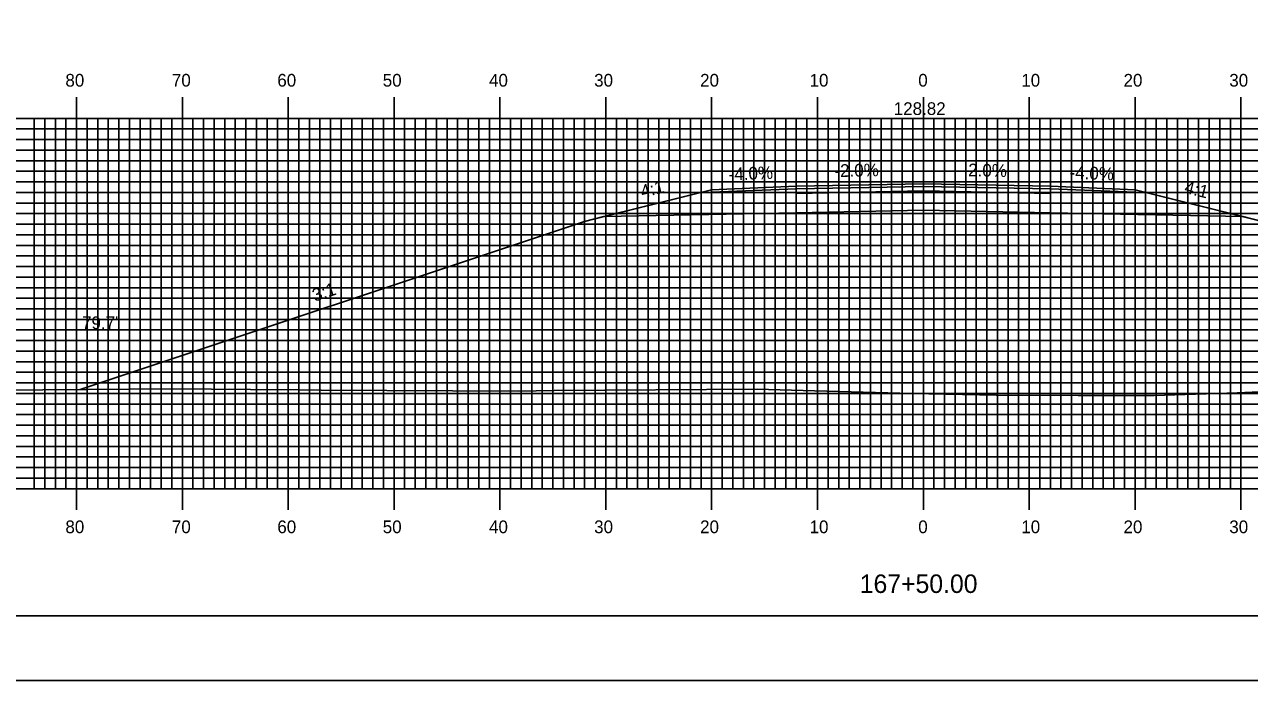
# Model space of a CAD drawing. Extents: x 1781860 to 1782203, y 442591 to 442811.
# Drawn here: x 1781941 to 1782056.7, y 442590.5 to 442652.5 of the extents above; entities that cross this region are included whole.
import ezdxf

# ---------------------------------------------------------------- set-up
doc = ezdxf.new("R2010")
doc.units = 0
for name, color, linetype in [('ANNOTATION', 7, 'Continuous'), ('BORDER', 7, 'Continuous'), ('D_Roadway_Centerline', 7, 'Continuous'), ('D_Roadway_Centerline_Text', 7, 'Continuous'), ('D_Roadway_Edge_Shoulder', 7, 'Continuous'), ('D_Roadway_Edge_TW', 7, 'Continuous'), ('D_Roadway_Pavement', 7, 'Continuous'), ('D_Roadway_SlopeLines', 7, 'Continuous'), ('D_Roadway_SubGrade', 7, 'Continuous'), ('D_Text_Standard', 7, 'Continuous'), ('H_V ANNOTATION', 7, 'Continuous'), ('MAJOR', 7, 'Continuous'), ('MINOR', 7, 'Continuous'), ('PLOT BOUNDARY', 7, 'Continuous'), ('S_Roadway_Centerline', 7, 'Continuous')]:
    doc.layers.add(name, color=color, linetype=linetype)

msp = doc.modelspace()

# ---------------------------------------------------------------- linework, layer by layer
at = {"layer": 'BORDER'}
msp.add_lwpolyline([(1781876.32, 442596.67), (1782196.32, 442596.67), (1782196.32, 442806.67), (1781876.32, 442806.67)], close=True, dxfattribs=at)
at = {"layer": 'D_Roadway_Centerline'}
msp.add_lwpolyline([(1781946.27, 442618.04), (1781993.92, 442633.93), (1781995.75, 442634.38), (1782005.92, 442636.93), (1782013.92, 442637.25), (1782025.92, 442637.49), (1782037.92, 442637.25), (1782045.92, 442636.93), (1782056.09, 442634.38), (1782057.92, 442633.93), (1782104.84, 442618.29)], dxfattribs=at)
at = {"layer": 'D_Roadway_Edge_Shoulder'}
for points in [[(1782013.92, 442637.25), (1782005.92, 442636.93), (1782005.92, 442636.68), (1782013.92, 442637)], [(1782037.92, 442637.25), (1782045.92, 442636.93), (1782045.92, 442636.68), (1782037.92, 442637)]]:
    msp.add_lwpolyline(points, close=True, dxfattribs=at)
at = {"layer": 'D_Roadway_Edge_TW'}
msp.add_lwpolyline([(1782013.92, 442637), (1782013.92, 442637.25), (1782025.92, 442637.49), (1782037.92, 442637.25), (1782037.92, 442637), (1782025.92, 442637.24)], close=True, dxfattribs=at)
at = {"layer": 'D_Roadway_Pavement'}
msp.add_lwpolyline([(1782013.92, 442636.58), (1782013.92, 442637), (1782025.92, 442637.24), (1782037.92, 442637), (1782037.92, 442636.58), (1782025.92, 442636.82)], close=True, dxfattribs=at)
at = {"layer": 'D_Roadway_SlopeLines'}
for points in [[(1782005.92, 442636.93), (1781993.92, 442633.93), (1781946.27, 442618.04)], [(1782045.92, 442636.93), (1782057.92, 442633.93), (1782104.84, 442618.29)]]:
    msp.add_lwpolyline(points, dxfattribs=at)
at = {"layer": 'D_Roadway_SubGrade'}
msp.add_lwpolyline([(1782013.92, 442634.75), (1781995.75, 442634.38), (1782005.92, 442636.93), (1782005.92, 442636.68), (1782013.92, 442637), (1782025.92, 442637.24), (1782037.92, 442637), (1782045.92, 442636.68), (1782045.92, 442636.93), (1782056.09, 442634.38), (1782037.92, 442634.75), (1782025.92, 442634.99)], close=True, dxfattribs=at)
at = {"layer": 'MAJOR'}
for p, q in [((1781945.92, 442645.67), (1781945.92, 442643.67)), ((1781955.92, 442645.67), (1781955.92, 442643.67)), ((1781965.92, 442645.67), (1781965.92, 442643.67)), ((1781975.92, 442645.67), (1781975.92, 442643.67)), ((1781985.92, 442645.67), (1781985.92, 442643.67)), ((1781995.92, 442645.67), (1781995.92, 442643.67)), ((1782005.92, 442645.67), (1782005.92, 442643.67)), ((1782015.92, 442645.67), (1782015.92, 442643.67)), ((1782025.92, 442645.67), (1782025.92, 442643.67)), ((1782035.92, 442645.67), (1782035.92, 442643.67)), ((1782045.92, 442645.67), (1782045.92, 442643.67)), ((1782055.92, 442645.67), (1782055.92, 442643.67)), ((1781885.92, 442643.67), (1782165.92, 442643.67)), ((1781885.92, 442643.67), (1782165.92, 442643.67)), ((1781945.92, 442608.67), (1781945.92, 442643.67)), ((1781955.92, 442608.67), (1781955.92, 442643.67)), ((1781965.92, 442608.67), (1781965.92, 442643.67)), ((1781975.92, 442608.67), (1781975.92, 442643.67)), ((1781985.92, 442608.67), (1781985.92, 442643.67)), ((1781995.92, 442608.67), (1781995.92, 442643.67)), ((1782005.92, 442608.67), (1782005.92, 442643.67)), ((1782015.92, 442608.67), (1782015.92, 442643.67)), ((1782025.92, 442608.67), (1782025.92, 442643.67)), ((1782035.92, 442608.67), (1782035.92, 442643.67)), ((1782045.92, 442608.67), (1782045.92, 442643.67)), ((1782055.92, 442608.67), (1782055.92, 442643.67)), ((1781885.92, 442638.67), (1782165.92, 442638.67)), ((1781885.92, 442633.67), (1782165.92, 442633.67)), ((1781885.92, 442628.67), (1782165.92, 442628.67)), ((1781885.92, 442623.67), (1782165.92, 442623.67)), ((1781885.92, 442618.67), (1782165.92, 442618.67)), ((1781885.92, 442613.67), (1782165.92, 442613.67)), ((1781885.92, 442608.67), (1782165.92, 442608.67)), ((1781885.92, 442608.67), (1782165.92, 442608.67)), ((1781945.92, 442606.66), (1781945.92, 442608.67)), ((1781955.92, 442606.66), (1781955.92, 442608.67)), ((1781965.92, 442606.66), (1781965.92, 442608.67)), ((1781975.92, 442606.66), (1781975.92, 442608.67)), ((1781985.92, 442606.66), (1781985.92, 442608.67)), ((1781995.92, 442606.66), (1781995.92, 442608.67)), ((1782005.92, 442606.66), (1782005.92, 442608.67)), ((1782015.92, 442606.66), (1782015.92, 442608.67)), ((1782025.92, 442606.66), (1782025.92, 442608.67)), ((1782035.92, 442606.66), (1782035.92, 442608.67)), ((1782045.92, 442606.66), (1782045.92, 442608.67)), ((1782055.92, 442606.66), (1782055.92, 442608.67))]:
    msp.add_line(p, q, dxfattribs=at)
at = {"layer": 'MINOR'}
for p, q in [((1781941.92, 442608.67), (1781941.92, 442643.67)), ((1781942.92, 442608.67), (1781942.92, 442643.67)), ((1781943.92, 442608.67), (1781943.92, 442643.67)), ((1781944.92, 442608.67), (1781944.92, 442643.67)), ((1781946.92, 442608.67), (1781946.92, 442643.67)), ((1781947.92, 442608.67), (1781947.92, 442643.67)), ((1781948.92, 442608.67), (1781948.92, 442643.67)), ((1781949.92, 442608.67), (1781949.92, 442643.67)), ((1781950.92, 442608.67), (1781950.92, 442643.67)), ((1781951.92, 442608.67), (1781951.92, 442643.67)), ((1781952.92, 442608.67), (1781952.92, 442643.67)), ((1781953.92, 442608.67), (1781953.92, 442643.67)), ((1781954.92, 442608.67), (1781954.92, 442643.67)), ((1781956.92, 442608.67), (1781956.92, 442643.67)), ((1781957.92, 442608.67), (1781957.92, 442643.67)), ((1781958.92, 442608.67), (1781958.92, 442643.67)), ((1781959.92, 442608.67), (1781959.92, 442643.67)), ((1781960.92, 442608.67), (1781960.92, 442643.67)), ((1781961.92, 442608.67), (1781961.92, 442643.67)), ((1781962.92, 442608.67), (1781962.92, 442643.67)), ((1781963.92, 442608.67), (1781963.92, 442643.67)), ((1781964.92, 442608.67), (1781964.92, 442643.67)), ((1781966.92, 442608.67), (1781966.92, 442643.67)), ((1781967.92, 442608.67), (1781967.92, 442643.67)), ((1781968.92, 442608.67), (1781968.92, 442643.67)), ((1781969.92, 442608.67), (1781969.92, 442643.67)), ((1781970.92, 442608.67), (1781970.92, 442643.67)), ((1781971.92, 442608.67), (1781971.92, 442643.67)), ((1781972.92, 442608.67), (1781972.92, 442643.67)), ((1781973.92, 442608.67), (1781973.92, 442643.67)), ((1781974.92, 442608.67), (1781974.92, 442643.67)), ((1781976.92, 442608.67), (1781976.92, 442643.67)), ((1781977.92, 442608.67), (1781977.92, 442643.67)), ((1781978.92, 442608.67), (1781978.92, 442643.67)), ((1781979.92, 442608.67), (1781979.92, 442643.67)), ((1781980.92, 442608.67), (1781980.92, 442643.67)), ((1781981.92, 442608.67), (1781981.92, 442643.67)), ((1781982.92, 442608.67), (1781982.92, 442643.67)), ((1781983.92, 442608.67), (1781983.92, 442643.67)), ((1781984.92, 442608.67), (1781984.92, 442643.67)), ((1781986.92, 442608.67), (1781986.92, 442643.67)), ((1781987.92, 442608.67), (1781987.92, 442643.67)), ((1781988.92, 442608.67), (1781988.92, 442643.67)), ((1781989.92, 442608.67), (1781989.92, 442643.67)), ((1781990.92, 442608.67), (1781990.92, 442643.67)), ((1781991.92, 442608.67), (1781991.92, 442643.67)), ((1781992.92, 442608.67), (1781992.92, 442643.67)), ((1781993.92, 442608.67), (1781993.92, 442643.67)), ((1781994.92, 442608.67), (1781994.92, 442643.67)), ((1781996.92, 442608.67), (1781996.92, 442643.67)), ((1781997.92, 442608.67), (1781997.92, 442643.67)), ((1781998.92, 442608.67), (1781998.92, 442643.67)), ((1781999.92, 442608.67), (1781999.92, 442643.67)), ((1782000.92, 442608.67), (1782000.92, 442643.67)), ((1782001.92, 442608.67), (1782001.92, 442643.67)), ((1782002.92, 442608.67), (1782002.92, 442643.67)), ((1782003.92, 442608.67), (1782003.92, 442643.67)), ((1782004.92, 442608.67), (1782004.92, 442643.67)), ((1782006.92, 442608.67), (1782006.92, 442643.67)), ((1782007.92, 442608.67), (1782007.92, 442643.67)), ((1782008.92, 442608.67), (1782008.92, 442643.67)), ((1782009.92, 442608.67), (1782009.92, 442643.67)), ((1782010.92, 442608.67), (1782010.92, 442643.67)), ((1782011.92, 442608.67), (1782011.92, 442643.67)), ((1782012.92, 442608.67), (1782012.92, 442643.67)), ((1782013.92, 442608.67), (1782013.92, 442643.67)), ((1782014.92, 442608.67), (1782014.92, 442643.67)), ((1782016.92, 442608.67), (1782016.92, 442643.67)), ((1782017.92, 442608.67), (1782017.92, 442643.67)), ((1782018.92, 442608.67), (1782018.92, 442643.67)), ((1782019.92, 442608.67), (1782019.92, 442643.67)), ((1782020.92, 442608.67), (1782020.92, 442643.67)), ((1782021.92, 442608.67), (1782021.92, 442643.67)), ((1782022.92, 442608.67), (1782022.92, 442643.67)), ((1782023.92, 442608.67), (1782023.92, 442643.67)), ((1782024.92, 442608.67), (1782024.92, 442643.67)), ((1782026.92, 442608.67), (1782026.92, 442643.67)), ((1782027.92, 442608.67), (1782027.92, 442643.67)), ((1782028.92, 442608.67), (1782028.92, 442643.67)), ((1782029.92, 442608.67), (1782029.92, 442643.67)), ((1782030.92, 442608.67), (1782030.92, 442643.67)), ((1782031.92, 442608.67), (1782031.92, 442643.67)), ((1782032.92, 442608.67), (1782032.92, 442643.67)), ((1782033.92, 442608.67), (1782033.92, 442643.67)), ((1782034.92, 442608.67), (1782034.92, 442643.67)), ((1782036.92, 442608.67), (1782036.92, 442643.67)), ((1782037.92, 442608.67), (1782037.92, 442643.67)), ((1782038.92, 442608.67), (1782038.92, 442643.67)), ((1782039.92, 442608.67), (1782039.92, 442643.67)), ((1782040.92, 442608.67), (1782040.92, 442643.67)), ((1782041.92, 442608.67), (1782041.92, 442643.67)), ((1782042.92, 442608.67), (1782042.92, 442643.67)), ((1782043.92, 442608.67), (1782043.92, 442643.67)), ((1782044.92, 442608.67), (1782044.92, 442643.67)), ((1782046.92, 442608.67), (1782046.92, 442643.67)), ((1782047.92, 442608.67), (1782047.92, 442643.67)), ((1782048.92, 442608.67), (1782048.92, 442643.67)), ((1782049.92, 442608.67), (1782049.92, 442643.67)), ((1782050.92, 442608.67), (1782050.92, 442643.67)), ((1782051.92, 442608.67), (1782051.92, 442643.67)), ((1782052.92, 442608.67), (1782052.92, 442643.67)), ((1782053.92, 442608.67), (1782053.92, 442643.67)), ((1782054.92, 442608.67), (1782054.92, 442643.67)), ((1781885.92, 442642.67), (1782165.92, 442642.67)), ((1781885.92, 442641.67), (1782165.92, 442641.67)), ((1781885.92, 442640.67), (1782165.92, 442640.67)), ((1781885.92, 442639.67), (1782165.92, 442639.67)), ((1781885.92, 442637.67), (1782165.92, 442637.67)), ((1781885.92, 442636.67), (1782165.92, 442636.67)), ((1781885.92, 442635.67), (1782165.92, 442635.67)), ((1781885.92, 442634.67), (1782165.92, 442634.67)), ((1781885.92, 442632.67), (1782165.92, 442632.67)), ((1781885.92, 442631.67), (1782165.92, 442631.67)), ((1781885.92, 442630.67), (1782165.92, 442630.67)), ((1781885.92, 442629.67), (1782165.92, 442629.67)), ((1781885.92, 442627.67), (1782165.92, 442627.67)), ((1781885.92, 442626.67), (1782165.92, 442626.67)), ((1781885.92, 442625.67), (1782165.92, 442625.67)), ((1781885.92, 442624.67), (1782165.92, 442624.67)), ((1781885.92, 442622.67), (1782165.92, 442622.67)), ((1781885.92, 442621.67), (1782165.92, 442621.67)), ((1781885.92, 442620.67), (1782165.92, 442620.67)), ((1781885.92, 442619.67), (1782165.92, 442619.67)), ((1781885.92, 442617.67), (1782165.92, 442617.67)), ((1781885.92, 442616.67), (1782165.92, 442616.67)), ((1781885.92, 442615.67), (1782165.92, 442615.67)), ((1781885.92, 442614.67), (1782165.92, 442614.67)), ((1781885.92, 442612.67), (1782165.92, 442612.67)), ((1781885.92, 442611.67), (1782165.92, 442611.67)), ((1781885.92, 442610.67), (1782165.92, 442610.67)), ((1781885.92, 442609.67), (1782165.92, 442609.67))]:
    msp.add_line(p, q, dxfattribs=at)
at = {"layer": 'PLOT BOUNDARY'}
msp.add_lwpolyline([(1781860.13, 442590.55), (1782200.13, 442590.55), (1782200.13, 442810.55), (1781860.13, 442810.55)], close=True, dxfattribs=at)
at = {"layer": 'S_Roadway_Centerline'}
msp.add_lwpolyline([(1781885.92, 442618.55), (1781888.53, 442618.72), (1781896.56, 442619), (1781904.99, 442618.5), (1781908.14, 442618.21), (1781910.85, 442618.11), (1781919.43, 442618.01), (1781929.39, 442617.96), (1781931.41, 442618.01), (1781934.56, 442617.96), (1781954.99, 442618.1), (1781962.36, 442618.05), (1781966.96, 442618.03), (1781969.02, 442617.98), (1781987.63, 442617.88), (1781991.03, 442617.95), (1782010.21, 442618.07), (1782015.63, 442617.91), (1782024.85, 442617.66), (1782032.79, 442617.5), (1782040.55, 442617.47), (1782047.74, 442617.48), (1782055.57, 442617.74), (1782059.11, 442617.89)], dxfattribs=at)

# ---------------------------------------------------------------- texts
at = {"layer": 'ANNOTATION'}
for s, rotation, p in [('-2.0%', 1.1458, (1782017.53, 442638.12)), ('-2.0%', 358.8542, (1782029.61, 442638.21)), ('-4.0%', 2.2906, (1782007.55, 442637.79)), ('-4.0%', 357.7094, (1782039.71, 442637.98)), ('4:1', 14.0362, (1781999.37, 442636.15)), ('4:1', 345.9638, (1782050.51, 442636.64)), ('3:1', 18.4348, (1781968.43, 442626.34))]:
    msp.add_text(s, height=1.2, rotation=rotation, dxfattribs=at).set_placement(p)
at = {"layer": 'D_Roadway_Centerline'}
for s, p in [('C', (1782025.92, 442637.49)), ('L', (1782025.92, 442637.48))]:
    msp.add_text(s, height=0.0146, dxfattribs=at).set_placement(p)
at = {"layer": 'D_Roadway_Centerline_Text'}
msp.add_text('128.82', height=1.2, dxfattribs=at).set_placement((1782023.12, 442643.99))
at = {"layer": 'D_Text_Standard'}
msp.add_text("79.7'", height=1.2, dxfattribs=at).set_placement((1781946.44, 442623.75))
at = {"layer": 'H_V ANNOTATION'}
for s, height, p in [('80', 1.2, (1781944.87, 442646.67)), ('70', 1.2, (1781954.93, 442646.67)), ('60', 1.2, (1781964.89, 442646.67)), ('50', 1.2, (1781974.85, 442646.67)), ('40', 1.2, (1781984.89, 442646.67)), ('30', 1.2, (1781994.82, 442646.67)), ('20', 1.2, (1782004.83, 442646.67)), ('10', 1.2, (1782015.17, 442646.67)), ('0', 1.2, (1782025.44, 442646.67)), ('10', 1.2, (1782035.17, 442646.67)), ('20', 1.2, (1782044.83, 442646.67)), ('30', 1.2, (1782054.82, 442646.67)), ('80', 1.2, (1781944.87, 442604.47)), ('70', 1.2, (1781954.93, 442604.47)), ('60', 1.2, (1781964.89, 442604.47)), ('50', 1.2, (1781974.85, 442604.47)), ('40', 1.2, (1781984.89, 442604.47)), ('30', 1.2, (1781994.82, 442604.47)), ('20', 1.2, (1782004.83, 442604.47)), ('10', 1.2, (1782015.17, 442604.47)), ('0', 1.2, (1782025.44, 442604.47)), ('10', 1.2, (1782035.17, 442604.47)), ('20', 1.2, (1782044.83, 442604.47)), ('30', 1.2, (1782054.82, 442604.47)), ('167+50.00', 1.75, (1782019.91, 442598.82))]:
    msp.add_text(s, height=height, dxfattribs=at).set_placement(p)

doc.saveas('drawing.dxf')
